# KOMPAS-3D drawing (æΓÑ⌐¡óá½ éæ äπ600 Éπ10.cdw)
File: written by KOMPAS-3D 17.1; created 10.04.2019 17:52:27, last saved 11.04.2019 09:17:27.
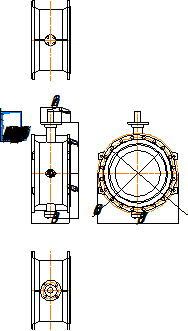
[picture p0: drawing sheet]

Sheet 1: A4, portrait

Title block, sheet 1: name: Стейнвал ВС Ду600 Ру10; material: Внимание! Данный продукт является объектом авторского права ООО «Торговый Дом АДЛ». / Запрещается изменение, копирование, распространение / (в том числе путем копирования на другие сайты и ресурсы в Интернете) / или любое иное использование информации и объектов без предварительного / согласия правообладателя (ООО «Торговый Дом АДЛ»).; mass: 291,06; sheets: 1; organisation: ООО "Торговый дом АДЛ"; sheet format: A4; stored path: \\adlc.lan\data\АДЛ_ПКД\3D-модели\ADL production\Дисковые поворотные затворы СТЕЙНВАЛ\Двухэксцентриковый ВС\KOMPAS 2D\Стейнвал ВС Ду600 Ру10.cdw

Views: Вид 1, Проекционный вид 2, Проекционный вид 3
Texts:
  user
Dimensions and other numbers on the sheet: 60; 210; 510; 450; 110; 380; 1:1; 1; 291,06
